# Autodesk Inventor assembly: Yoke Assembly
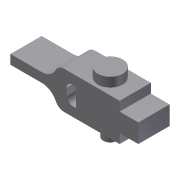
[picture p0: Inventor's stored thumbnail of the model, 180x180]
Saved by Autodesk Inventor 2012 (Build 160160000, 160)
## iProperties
Created: 2012-02
Part Number: Yoke Assembly
Document SubType Name: Assembly
Designer: cadcim
Author: cadcim
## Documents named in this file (4)
- C:\ANSYS_WB\c10\Tut03\Assembly\Yoke Assembly.iam
- C:\ANSYS_WB\c10\Tut03\Assembly\Yoke.ipt
- C:\ANSYS_WB\c10\Tut03\Assembly\Stem.ipt
- C:\ANSYS_WB\c10\Tut03\Assembly\pIN.ipt
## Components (3 placed, 3 different names)
1. Yoke:1 — Mate:3, Mate:4, Angle:1, Mate:5, Mate:6
2. Stem:1 — Mate:3, Mate:4, Angle:1
3. pIN:1 — Mate:5, Mate:6
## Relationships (5: Mate 4, Angle 1)
- Mate:3: Yoke:1 ↔ Stem:1
- Mate:4: Yoke:1 ↔ Stem:1
- Angle:1: Yoke:1 ↔ Stem:1
- Mate:5: Yoke:1 ↔ pIN:1
- Mate:6: Yoke:1 ↔ pIN:1
